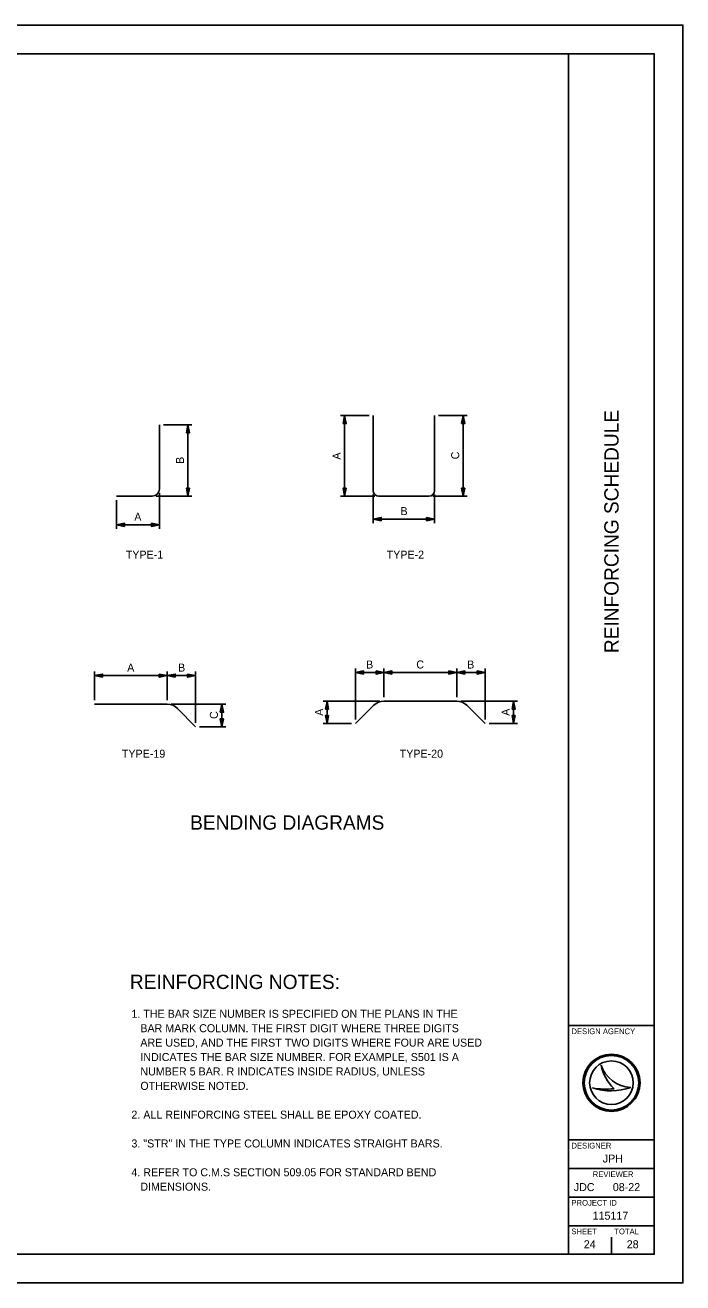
# Model space of a CAD drawing. Extents: x 0 to 34, y 0 to 22.
# Drawn here: x 22.49 to 34, y 0 to 22 of the extents above; entities that cross this region are included whole.
import ezdxf

# ---------------------------------------------------------------- set-up
doc = ezdxf.new("R2010")
doc.units = 0
for name, color, linetype in [('BR_P_Gen_NonPerf_Pipe', 7, 'Continuous'), ('BR_P_Gen_Text', 7, 'Continuous'), ('SH_Border', 7, 'Continuous'), ('SH_Cut_Line', 7, 'Continuous'), ('SH_Data', 7, 'Continuous'), ('TX_P_10', 7, 'Continuous')]:
    doc.layers.add(name, color=color, linetype=linetype)

msp = doc.modelspace()

# ---------------------------------------------------------------- linework, layer by layer
at = {"layer": 'BR_P_Gen_Text'}
for p, q in [((24.838, 13.885), (24.838, 15.01)), ((24.908, 15.01), (25.408, 15.01)), ((25.338, 15.01), (25.338, 13.76)), ((28.51, 15.171), (28.01, 15.171)), ((28.08, 15.171), (28.08, 13.76)), ((28.58, 15.171), (28.58, 13.86)), ((29.655, 13.86), (29.655, 15.171)), ((29.725, 15.171), (30.225, 15.171)), ((30.155, 15.171), (30.155, 13.76)), ((24.088, 13.76), (24.713, 13.76)), ((24.088, 13.69), (24.088, 13.19)), ((24.783, 13.76), (25.408, 13.76)), ((24.838, 13.815), (24.838, 13.19)), ((28.61, 13.76), (28.01, 13.76)), ((28.58, 13.79), (28.58, 13.29)), ((28.68, 13.76), (29.555, 13.76)), ((29.625, 13.76), (30.225, 13.76)), ((29.655, 13.79), (29.655, 13.29)), ((24.088, 13.26), (24.838, 13.26)), ((28.58, 13.36), (29.655, 13.36)), ((23.703, 10.192), (23.703, 10.692)), ((24.975, 10.622), (23.703, 10.622)), ((24.975, 10.192), (24.975, 10.692)), ((24.975, 10.192), (24.975, 10.692)), ((24.975, 10.622), (25.472, 10.622)), ((25.472, 9.797), (25.472, 10.692)), ((28.272, 9.852), (28.272, 10.746)), ((28.272, 10.676), (28.769, 10.676)), ((28.769, 10.246), (28.769, 10.746)), ((28.769, 10.246), (28.769, 10.746)), ((28.769, 10.676), (30.041, 10.676)), ((30.041, 10.246), (30.041, 10.746)), ((30.041, 10.246), (30.041, 10.746)), ((30.538, 10.676), (30.041, 10.676)), ((30.538, 9.852), (30.538, 10.746)), ((24.975, 10.122), (23.703, 10.122)), ((25.045, 10.122), (26.002, 10.122)), ((25.932, 9.727), (25.932, 10.122)), ((28.699, 10.176), (27.702, 10.176)), ((27.772, 10.176), (27.772, 9.782)), ((30.041, 10.176), (28.769, 10.176)), ((30.111, 10.176), (31.108, 10.176)), ((31.038, 10.176), (31.038, 9.782)), ((25.152, 10.048), (25.472, 9.727)), ((28.593, 10.103), (28.272, 9.782)), ((30.218, 10.103), (30.538, 9.782)), ((25.542, 9.727), (26.002, 9.727)), ((28.202, 9.782), (27.702, 9.782)), ((30.608, 9.782), (31.108, 9.782))]:
    msp.add_line(p, q, dxfattribs=at)
for points in [[(25.31, 14.87), (25.338, 15.01), (25.366, 14.87)], [(28.052, 15.031), (28.08, 15.171), (28.108, 15.031)], [(30.127, 15.031), (30.155, 15.171), (30.183, 15.031)], [(25.366, 13.9), (25.338, 13.76), (25.31, 13.9)], [(28.108, 13.9), (28.08, 13.76), (28.052, 13.9)], [(30.183, 13.9), (30.155, 13.76), (30.127, 13.9)], [(24.228, 13.232), (24.088, 13.26), (24.228, 13.288)], [(24.698, 13.288), (24.838, 13.26), (24.698, 13.232)], [(28.72, 13.332), (28.58, 13.36), (28.72, 13.388)], [(29.515, 13.388), (29.655, 13.36), (29.515, 13.332)], [(23.843, 10.594), (23.703, 10.622), (23.843, 10.65)], [(24.835, 10.65), (24.975, 10.622), (24.835, 10.594)], [(25.115, 10.594), (24.975, 10.622), (25.115, 10.65)], [(25.332, 10.65), (25.472, 10.622), (25.332, 10.594)], [(28.412, 10.648), (28.272, 10.676), (28.412, 10.704)], [(28.629, 10.704), (28.769, 10.676), (28.629, 10.648)], [(28.909, 10.648), (28.769, 10.676), (28.909, 10.704)], [(29.901, 10.704), (30.041, 10.676), (29.901, 10.648)], [(30.181, 10.648), (30.041, 10.676), (30.181, 10.704)], [(30.398, 10.704), (30.538, 10.676), (30.398, 10.648)], [(25.904, 9.982), (25.932, 10.122), (25.96, 9.982)], [(27.744, 10.036), (27.772, 10.176), (27.8, 10.036)], [(31.01, 10.036), (31.038, 10.176), (31.066, 10.036)], [(27.8, 9.922), (27.772, 9.782), (27.744, 9.922)], [(31.066, 9.922), (31.038, 9.782), (31.01, 9.922)], [(25.96, 9.867), (25.932, 9.727), (25.904, 9.867)]]:
    msp.add_lwpolyline(points, close=True, dxfattribs=at)
for centre, radius, start, end in [((24.713, 13.885), 0.125, 270, 360), ((28.68, 13.86), 0.1, 180, 270), ((29.555, 13.86), 0.1, 270, 360), ((24.975, 9.872), 0.25, 45, 90), ((28.769, 9.926), 0.25, 90, 135), ((30.041, 9.926), 0.25, 45, 90)]:
    msp.add_arc(centre, radius, start, end, dxfattribs=at)
at = {"layer": 'SH_Border'}
for p, q in [((32, 0.5), (32, 21.5)), ((32, 4.5), (33.5, 4.5)), ((32, 2.5), (33.5, 2.5)), ((32, 2), (33.5, 2)), ((32, 1.5), (33.5, 1.5)), ((32, 1), (33.5, 1))]:
    msp.add_line(p, q, dxfattribs=at)
msp.add_lwpolyline([(1.5, 21.5), (33.5, 21.5), (33.5, 0.5), (1.5, 0.5)], close=True, dxfattribs=at)
at = {"layer": 'SH_Cut_Line'}
msp.add_lwpolyline([(0, 0), (34, 0), (34, 22), (0, 22)], close=True, dxfattribs=at)
at = {"layer": 'SH_Data'}
for p, q in [((32.567, 3.81), (32.567, 3.81)), ((32.417, 3.41), (32.417, 3.41)), ((32.75, 3.5), (32.75, 3.5)), ((33.087, 3.419), (33.087, 3.419)), ((32.375, 0.675), (32.375, 0.675)), ((32.75, 0.5), (32.75, 0.8))]:
    msp.add_line(p, q, dxfattribs=at)
for radius in [0.5, 0.477, 0.477, 0.382]:
    msp.add_circle((32.75, 3.5), radius, dxfattribs=at)
for centre, radius, start, end in [((33.116, 3.998), 0.58, 198.9257, 198.9319), ((33.347, 3.97), 0.796, 191.6379, 191.6421), ((33.116, 3.998), 0.58, 198.9319, 267.1657), ((33.347, 3.97), 0.796, 191.6421, 226.0947), ((32.739, 4.37), 1.013, 251.4576, 290.0832), ((32.648, 4.654), 1.266, 259.4964, 259.4995), ((32.739, 4.37), 1.013, 251.4527, 251.4576), ((32.648, 4.654), 1.266, 259.4995, 276.6672)]:
    msp.add_arc(centre, radius, start, end, dxfattribs=at)

# ---------------------------------------------------------------- texts
at = {"layer": 'BR_P_Gen_NonPerf_Pipe'}
for s, p in [('1. THE BAR SIZE NUMBER IS SPECIFIED ON THE PLANS IN THE', (24.348, 4.636)), ('   BAR MARK COLUMN. THE FIRST DIGIT WHERE THREE DIGITS', (24.348, 4.384)), ('   ARE USED, AND THE FIRST TWO DIGITS WHERE FOUR ARE USED ', (24.348, 4.132)), ('   INDICATES THE BAR SIZE NUMBER. FOR EXAMPLE, S501 IS A ', (24.348, 3.88)), ('   NUMBER 5 BAR. R INDICATES INSIDE RADIUS, UNLESS', (24.348, 3.628)), ('   OTHERWISE NOTED.', (24.348, 3.376)), ('2. ALL REINFORCING STEEL SHALL BE EPOXY COATED.', (24.348, 2.872)), ('3. "STR" IN THE TYPE COLUMN INDICATES STRAIGHT BARS.', (24.348, 2.368)), ('4. REFER TO C.M.S SECTION 509.05 FOR STANDARD BEND ', (24.348, 1.864)), ('   DIMENSIONS.', (24.348, 1.612))]:
    msp.add_text(s, height=0.14, dxfattribs=at).set_placement(p)
at = {"layer": 'BR_P_Gen_Text'}
for s, p in [('A', (28.01, 14.4)), ('C', (30.085, 14.405)), ('B', (25.268, 14.325)), ('C', (25.862, 9.864)), ('A', (27.702, 9.919)), ('A', (30.968, 9.919))]:
    msp.add_text(s, height=0.14, rotation=90, dxfattribs=at).set_placement(p)
for s, p in [('A', (24.398, 13.33)), ('B', (29.057, 13.43)), ('A', (24.274, 10.692)), ('B', (25.164, 10.692)), ('B', (28.455, 10.746)), ('C', (29.334, 10.746)), ('B', (30.224, 10.746))]:
    msp.add_text(s, height=0.14, dxfattribs=at).set_placement(p)
at = {"layer": 'SH_Data'}
msp.add_text('REINFORCING SCHEDULE', height=0.25, rotation=90, dxfattribs=at).set_placement((32.875, 11.015))
for s, height, p in [('BENDING DIAGRAMS', 0.25, (25.376, 7.927)), ('REINFORCING NOTES:', 0.25, (24.321, 5.14)), ('DESIGN AGENCY', 0.1, (32.05, 4.35)), ('DESIGNER', 0.1, (32.05, 2.35)), ('JPH', 0.14, (32.598, 2.105)), ('REVIEWER', 0.1, (32.422, 1.85)), ('JDC', 0.14, (32.091, 1.605)), ('08-22', 0.14, (32.774, 1.605)), ('PROJECT ID', 0.1, (32.05, 1.35)), ('115117', 0.14, (32.42, 1.105)), ('SHEET', 0.1, (32.05, 0.85)), ('TOTAL', 0.1, (32.8, 0.85)), ('24', 0.14, (32.266, 0.605)), ('28', 0.14, (33.018, 0.605))]:
    msp.add_text(s, height=height, dxfattribs=at).set_placement(p)
at = {"layer": 'TX_P_10'}
for s, p in [('TYPE-1', (24.249, 12.668)), ('TYPE-2', (28.815, 12.668)), ('TYPE-19', (24.181, 9.186)), ('TYPE-20', (29.043, 9.186))]:
    msp.add_text(s, height=0.14, dxfattribs=at).set_placement(p)

doc.saveas('drawing.dxf')
